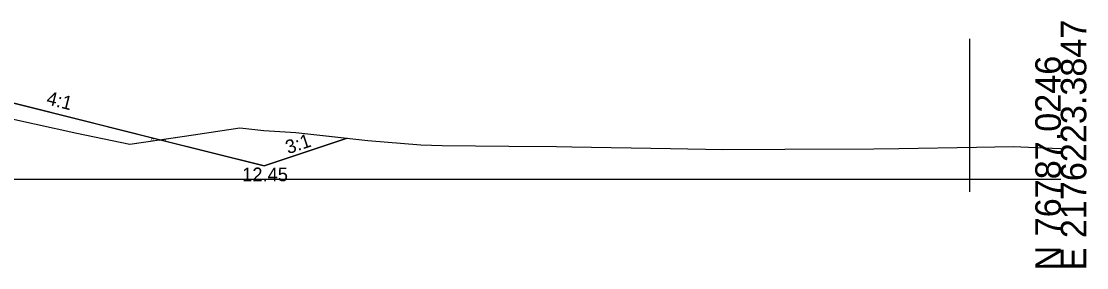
# Model space of a CAD drawing. Extents: x 2177029 to 2201446, y 59897 to 78390.
# Drawn here: x 2199328.6 to 2199445.6, y 66897.6 to 66924.6 of the extents above; entities that cross this region are included whole.
import ezdxf

# ---------------------------------------------------------------- set-up
doc = ezdxf.new("R2010")
doc.units = 0
for name, color, linetype in [('Exist Cross Section Cell', 7, 'Continuous'), ('Exist PHM Roadway Shape', 7, 'Continuous'), ('Exist XS Ground Line', 7, 'Continuous'), ('Prop CMT Guardrail Widen Shoulder', 7, 'Continuous'), ('Prop CMT Top Wall Envelope', 7, 'Continuous'), ('Prop Hatching', 7, 'Continuous'), ('Prop XS Side Slope Text', 7, 'Continuous'), ('Scratch_Level_2', 7, 'Continuous')]:
    doc.layers.add(name, color=color, linetype=linetype)

msp = doc.modelspace()

# ---------------------------------------------------------------- linework, layer by layer
at = {"layer": 'Exist Cross Section Cell'}
msp.add_line((2199242.73, 66907.31), (2199442.73, 66907.31), dxfattribs=at)
at = {"layer": 'Exist XS Ground Line'}
msp.add_lwpolyline([(2199325.37, 66914.4), (2199334.7, 66912.35), (2199340.55, 66911.16), (2199347.51, 66912.18), (2199352.62, 66912.92), (2199355.26, 66912.66), (2199358.74, 66912.41), (2199366.67, 66911.55), (2199372.46, 66911.08), (2199374.82, 66911.01), (2199382.13, 66910.92), (2199387.36, 66910.88), (2199389.04, 66910.86), (2199399.89, 66910.66), (2199405.63, 66910.58), (2199412.42, 66910.59), (2199422.21, 66910.65), (2199424.96, 66910.69), (2199433.48, 66910.82), (2199437.49, 66910.88), (2199440.03, 66910.78), (2199442.73, 66910.67)], dxfattribs=at)
at = {"layer": 'Prop Hatching'}
msp.add_line((2199355.29, 66908.76), (2199364.4, 66911.8), dxfattribs=at)
msp.add_lwpolyline([(2199318.74, 66917.4), (2199320.74, 66917.4), (2199355.29, 66908.76)], dxfattribs=at)
at = {"layer": 'Prop XS Side Slope Text'}
for points in [[(2199340.55, 66911.16), (2199343.79, 66911.64), (2199324.74, 66916.4), (2199319.74, 66916.4), (2199309.61, 66916.4), (2199317.15, 66916.2), (2199325.37, 66914.4), (2199334.7, 66912.35)], [(2199355.26, 66912.66), (2199358.74, 66912.41), (2199364.4, 66911.8), (2199355.29, 66908.76), (2199343.79, 66911.64), (2199347.51, 66912.18), (2199352.62, 66912.92)]]:
    msp.add_lwpolyline(points, close=True, dxfattribs=at)
at = {"layer": 'Scratch_Level_2'}
msp.add_line((2199432.73, 66905.94), (2199432.73, 66922.68), dxfattribs=at)

# ---------------------------------------------------------------- texts
at = {"layer": 'Exist Cross Section Cell'}
for s, p in [('E 2176223.3847', (2199445.53, 66897.31)), ('N 76787.0246', (2199442.73, 66897.31))]:
    msp.add_text(s, height=2.8, rotation=90, dxfattribs=at).set_placement(p)
at = {"layer": 'Exist PHM Roadway Shape'}
msp.add_text('RT_Slope_Fill', height=0.2, dxfattribs=at).set_placement((2199342.84, 66911.54))
at = {"layer": 'Prop CMT Guardrail Widen Shoulder'}
msp.add_text('4:1', height=1.5, rotation=345.9628, dxfattribs=at).set_placement((2199331.29, 66915.53))
at = {"layer": 'Prop CMT Top Wall Envelope'}
msp.add_text('3:1', height=1.5, rotation=18.4349, dxfattribs=at).set_placement((2199357.91, 66910.04))
msp.add_text('12.45', height=1.5, dxfattribs=at).set_placement((2199352.87, 66907.08))

doc.saveas('drawing.dxf')
